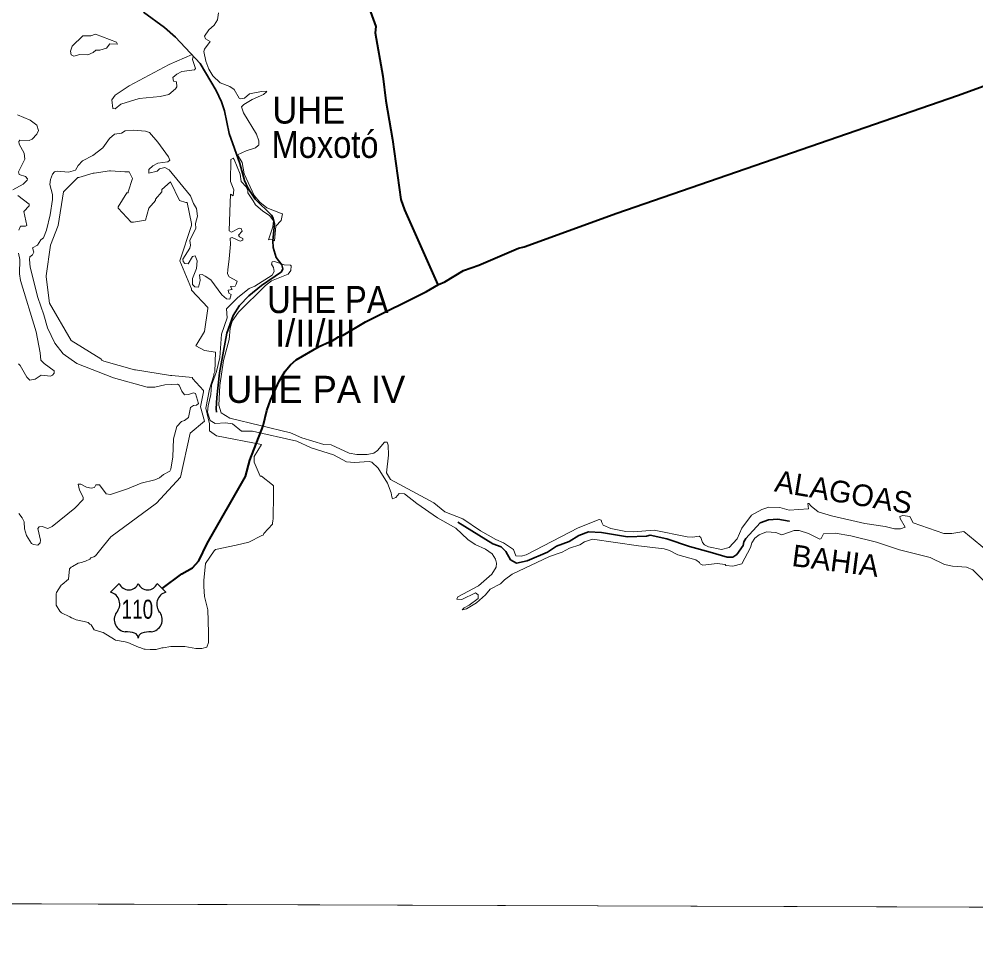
# Model space of a CAD drawing. Extents: x 553962 to 842807, y 8883888 to 9032388.
# Drawn here: x 580395 to 583927, y 8909822 to 8913255 of the extents above; entities that cross this region are included whole.
import ezdxf
from ezdxf.enums import TextEntityAlignment as Align

# ---------------------------------------------------------------- set-up
doc = ezdxf.new("R2010")
doc.units = 0
doc.header["$LTSCALE"] = 200
doc.linetypes.add('LONG_DASH_SHORT_DASH', pattern=[9.9, 6, -1.2, 1.5, -1.2])
doc.layers.add('6', color=7, linetype='Continuous', lineweight=13)

msp = doc.modelspace()

# ---------------------------------------------------------------- linework, layer by layer
at = {"layer": '6', "lineweight": 25}
for p, q in [((580732.9, 8911139.1), (580764.9, 8911171.1)), ((580904.8, 8911171.1), (580936.8, 8911139.1))]:
    msp.add_line(p, q, dxfattribs=at)
at = {"layer": '6'}
msp.add_line((574653.9, 8910009.3), (626625.7, 8909822.1), dxfattribs=at)
for points in [[(585645.8, 8921027.3), (574684.9, 8921064.7), (574653.9, 8910009.3), (585614.8, 8909969.8)], [(580677.4, 8913199.3), (580754.6, 8913169.1), (580757.7, 8913161.8), (580729.4, 8913163.2), (580717.7, 8913147), (580692.7, 8913140.2), (580677.9, 8913140.2), (580669, 8913131.7), (580648.6, 8913122.4), (580619.7, 8913123.6), (580597.1, 8913117.7), (580587.8, 8913122.8), (580585.2, 8913136.5), (580590.4, 8913155), (580629.9, 8913192.5), (580660.4, 8913193.7)], [(580749.7, 8912974.1), (580801.2, 8913008.5), (580948.9, 8913087.1), (581033.9, 8913124), (581037.3, 8913116.8), (581035.2, 8913105.4), (581045.7, 8913072.2), (581042.7, 8913067.9), (580996, 8913061.1), (580977.8, 8913051.8), (580962.2, 8913039.1), (580964.6, 8913025.5), (580976, 8913023.8), (580976.9, 8913004.7), (580972.7, 8912997.5), (580948.1, 8912976.6), (580915.4, 8912968.6), (580838.8, 8912961.7), (580770.9, 8912941.3), (580750.1, 8912923.1), (580741.6, 8912925.3), (580737.8, 8912956.3)]]:
    msp.add_lwpolyline(points, close=True, dxfattribs=at)
at = {"layer": '6', "linetype": 'LONG_DASH_SHORT_DASH', "lineweight": 35}
for points in [[(580854, 8913279.9), (580932.2, 8913223.8), (580972.1, 8913187.7), (581063.2, 8913090.6), (581122.5, 8912991.5), (581142, 8912949.8), (581153.2, 8912915.6), (581171, 8912832.2), (581209.9, 8912721.7), (581227.6, 8912659.4), (581239.2, 8912631.8), (581266.5, 8912590.3), (581326.2, 8912531.5), (581332.6, 8912519.4), (581337.8, 8912498.5), (581331.8, 8912436.4), (581333.1, 8912411.1), (581343.9, 8912375), (581365.1, 8912348.2), (581368.5, 8912332.5), (581364.2, 8912321.3), (581289.9, 8912271.7), (581243.5, 8912233.1), (581208.6, 8912197.7), (581185.2, 8912160.5), (581161.6, 8912095.9), (581134.3, 8911949.1), (581124.7, 8911857.9), (581122.5, 8911815.6), (581124, 8911803.1)], [(582014.6, 8911397.4), (582144.1, 8911317), (582174.9, 8911306.2), (582192.1, 8911288.9), (582208.6, 8911258.7), (582231.6, 8911246.5), (582271.2, 8911254.3), (582345.6, 8911286.3), (582378.5, 8911308.3), (582425.2, 8911326.1), (582461.6, 8911347.7), (582496.6, 8911362.4), (582544.5, 8911359.4), (582641.4, 8911343.8), (582710.6, 8911346), (582724.4, 8911349.4), (582786.7, 8911336.4), (582869.7, 8911307.5), (582946.6, 8911287.2), (583008.9, 8911268.1), (583029.6, 8911268.6), (583045.2, 8911277.6), (583067.7, 8911311.3), (583070.7, 8911325.2), (583077.6, 8911337.3), (583130.3, 8911394.8), (583161.9, 8911405.6), (583196.6, 8911409.1), (583238, 8911401.7), (583238.9, 8911401.7)]]:
    msp.add_lwpolyline(points, dxfattribs=at)
at = {"layer": '6'}
for points in [[(581309.8, 8912988.2), (581309.8, 8912988.2), (581289.7, 8912987.7), (581245.5, 8912978.7), (581227.2, 8912963.4), (581212, 8912960.1), (581207.2, 8912962.6), (581188.9, 8912994.9), (581172.8, 8913005.9), (581137.1, 8913019.9), (581110.7, 8913045.9), (581096, 8913070), (581084, 8913099.8), (581076.8, 8913135.4), (581079.3, 8913144), (581100.6, 8913172.4), (581083.2, 8913182.3), (581079.8, 8913192.1), (581095.1, 8913214.9), (581115, 8913232.4), (581127.7, 8913252.7), (581131.6, 8913278.4)], [(581277.8, 8912788.2), (581279.5, 8912789.6), (581280, 8912805.1), (581271, 8912830.4), (581223.8, 8912908.6), (581216.6, 8912930.4), (581224.7, 8912939.7), (581254.8, 8912957.9), (581296.7, 8912976.6), (581308.1, 8912986.6), (581309.8, 8912988.2)], [(580388.5, 8912901.4), (580436.2, 8912882.3), (580460.3, 8912862.7), (580466.7, 8912844), (580460.3, 8912829.6), (580443.8, 8912811), (580432.7, 8912806.3), (580397.9, 8912807.9), (580394.1, 8912802.5), (580395.3, 8912793), (580413.2, 8912759.9), (580416.6, 8912737.9), (580392.8, 8912690.9), (580395.3, 8912681.4), (580418.7, 8912673.7), (580425.9, 8912664.7), (580424.9, 8912660.4), (580409.4, 8912645.7), (580371.5, 8912623.9)], [(580896.6, 8911553.8), (580912.7, 8911561), (580928, 8911573.3), (580951, 8911585.2), (580955.3, 8911593.3), (580962.1, 8911639.2), (580965.5, 8911704.7), (580977.3, 8911751.3), (580993.9, 8911768.7), (581005.5, 8911772.6), (581020.3, 8911784.5), (581028.3, 8911821), (581038.6, 8911828.7), (581049.6, 8911829.9), (581056.8, 8911835.1), (581046.7, 8911872.7), (581039.4, 8911875.4), (581020.8, 8911869.1), (581005.8, 8911868.2), (580995.2, 8911881.4), (580986.3, 8911903.8), (580980.3, 8911907.2), (580933.2, 8911905.1), (580895.8, 8911896.2), (580867.6, 8911895.4), (580743.7, 8911929.8), (580608.6, 8911983.8), (580557.2, 8912019.4), (580527, 8912059), (580499.4, 8912115), (580486.1, 8912163.4), (580463.7, 8912227.1), (580435.7, 8912339.3), (580433.1, 8912367.4), (580435.2, 8912376.6), (580444.6, 8912384.8), (580449.3, 8912394.6), (580444.7, 8912409.9), (580462.4, 8912419.7), (580475.2, 8912439.6), (580484.5, 8912446.8), (580496.3, 8912475.7), (580510, 8912532.2), (580518.5, 8912588.3), (580518.5, 8912607), (580508.3, 8912644.4), (580510.9, 8912663), (580518.7, 8912681.9), (580525.8, 8912690.7), (580535.5, 8912693.2), (580577, 8912689.8), (580577, 8912689.8), (580602.6, 8912697.5), (580612.9, 8912714.1), (580629, 8912731.5), (580667.3, 8912751.5), (580704.2, 8912779), (580728.9, 8912814.4), (580747.1, 8912830.5), (580772.6, 8912833.5), (580786.6, 8912842.8), (580816.8, 8912845.3), (580861.8, 8912841.5), (580876.7, 8912835.6), (580907.3, 8912800.7), (580946.8, 8912745.9), (580951.8, 8912734.5), (580944.1, 8912728.4), (580907.7, 8912722.4), (580888.1, 8912713.2), (580873.7, 8912699.1), (580873.7, 8912686.1), (580905.1, 8912693.7), (580912.8, 8912702.2), (580933.6, 8912706.4), (580948.5, 8912698.3), (581027.9, 8912601.9), (581039, 8912573.9), (581050.5, 8912555), (581053.4, 8912527.1), (581046.2, 8912500.8), (581047.9, 8912483.1), (581025, 8912437.1), (581027.9, 8912419.8), (581024.9, 8912409), (580999.5, 8912368.6), (581000.8, 8912359.3), (581007.1, 8912353), (581019.3, 8912350.8), (581035.6, 8912378), (581045.2, 8912381), (581052.5, 8912362.4), (581049.6, 8912334.3), (581034.7, 8912296.8), (581034.8, 8912275.2), (581043.2, 8912266.3), (581057.1, 8912265), (581063.6, 8912289.2), (581060.7, 8912310.8), (581070.9, 8912312.5), (581081.6, 8912305.8)], [(581366.5, 8912535.8), (581309.1, 8912558.6), (581283.7, 8912578.6), (581262.3, 8912603.9), (581262.3, 8912603.9), (581225.9, 8912683.5), (581218.3, 8912725.1), (581201.7, 8912753.5), (581233.6, 8912768.4), (581267.9, 8912779.9), (581277.8, 8912788.2)], [(581172.7, 8912543.7), (581175, 8912608.9), (581185.1, 8912601.8), (581187.7, 8912624), (581174.9, 8912654.7), (581176.2, 8912736.1), (581185.3, 8912741.2), (581189.3, 8912737.1), (581210.6, 8912682.6), (581215.3, 8912655.5), (581233.2, 8912635.8), (581239.9, 8912622.3), (581240, 8912613.3), (581258.5, 8912584.3)], [(580733.2, 8911343.8), (580902, 8911467.3), (580990.8, 8911564.2), (581027.1, 8911725.6), (581079.6, 8911770), (581064.5, 8911823.6), (581075.6, 8911879), (581075.6, 8911883.1), (581035.2, 8911927.5), (581035.2, 8911931.5), (580958.5, 8911939.6), (580954.5, 8911939.6), (580825.3, 8911959.8), (580821.3, 8911959.8), (580708.3, 8911992), (580700.2, 8911996.1), (580696.2, 8912000.1), (580587.3, 8912068.7), (580506.6, 8912206), (580494.4, 8912302.9), (580494.4, 8912306.9), (580510.6, 8912419.9), (580538.8, 8912492.6), (580559, 8912617.7), (580611.5, 8912670.2), (580615.5, 8912670.2), (580668, 8912686.4), (580672, 8912686.4), (580728.5, 8912694.4), (580732.5, 8912694.4), (580785, 8912690.4), (580793.1, 8912690.4), (580797.1, 8912690.4), (580801.1, 8912690.4), (580813.2, 8912666.2), (580797.1, 8912617.7), (580797.1, 8912613.7), (580793.1, 8912613.7), (580760.8, 8912561.2), (580760.8, 8912557.2), (580809.2, 8912504.7), (580813.2, 8912504.7), (580817.3, 8912504.7), (580861.7, 8912512.8), (580873.8, 8912557.2), (580898, 8912585.4), (580898, 8912589.5), (580922.2, 8912617.7), (580922.2, 8912621.8), (580922.2, 8912625.8), (580954.5, 8912654.1), (580986.8, 8912585.4), (581011, 8912577.4), (581015, 8912577.4), (581031.2, 8912500.7), (581031.2, 8912496.6), (581031.2, 8912492.6), (580988.2, 8912362.7), (581031.2, 8912258.5), (581031.2, 8912254.4), (581091.7, 8912189.8), (581091.7, 8912185.8), (581079.6, 8912101), (581047.3, 8912048.6)], [(580389.8, 8912603.1), (580432.7, 8912571.7), (580432.5, 8912565.6), (580412.3, 8912544.5), (580423.3, 8912493.2), (580418.2, 8912489.8), (580400.4, 8912490.6), (580394.5, 8912476.2)], [(581258.5, 8912584.3), (581268.3, 8912568.8), (581295.3, 8912545.3), (581319, 8912529.6), (581333.8, 8912510.2), (581332.8, 8912500.7)], [(581218.2, 8912471.5), (581214.4, 8912482.3), (581208, 8912482.9), (581179.6, 8912467.7), (581170.2, 8912473.2), (581172.7, 8912543.7)], [(581337.2, 8912437), (581338.1, 8912436.6), (581342.3, 8912490.1), (581362.3, 8912511), (581366.8, 8912535.7), (581366.5, 8912535.8)], [(581169.9, 8912369.9), (581175.8, 8912423.6), (581174.5, 8912446.3), (581181.3, 8912448.5), (581211, 8912434.9), (581220.8, 8912438.5), (581220.4, 8912445.1), (581208.9, 8912451.1), (581205.5, 8912456.7), (581218.2, 8912471.5), (581218.2, 8912471.5)], [(581332.8, 8912500.7), (581331.5, 8912488.3), (581315.9, 8912439.5), (581316.2, 8912439.6), (581316.2, 8912440.5)], [(581316.2, 8912439.6), (581324.1, 8912442.3), (581337.2, 8912437)], [(580393.2, 8912391), (580397.9, 8912367.4), (580397, 8912313.8), (580400, 8912290.1), (580457.8, 8912099.8), (580473.1, 8912022.4), (580474.8, 8911995.7), (580487.1, 8911983.3), (580524.9, 8911956.1), (580524.5, 8911947.6), (580518.1, 8911940), (580510.8, 8911937), (580476, 8911940), (580454.4, 8911926), (580434.4, 8911921.7), (580423.8, 8911932.8), (580398.7, 8911976.5), (580392.2, 8911981.7)], [(581196.1, 8912276.3), (581200.4, 8912287), (581169.9, 8912302.8), (581163.9, 8912314.7), (581165.4, 8912328.8), (581169.9, 8912369.9)], [(581135.5, 8911901.6), (581149.3, 8911994.6), (581170.2, 8912071.5), (581173.7, 8912113.4), (581181.2, 8912140.2), (581205.4, 8912173.1), (581304.6, 8912271.9), (581326.6, 8912288.6), (581388, 8912312.8), (581398.3, 8912327.2), (581399.7, 8912343.6), (581396.9, 8912346.6), (581374.1, 8912347), (581338.1, 8912359.7), (581329.6, 8912358.2), (581327, 8912349.8), (581333.7, 8912337.4), (581336.7, 8912322.7), (581329, 8912309.2), (581265.5, 8912268.8), (581244.2, 8912259.8), (581202.1, 8912226.9), (581160.5, 8912185.1), (581163.3, 8912151.7), (581142.6, 8912091.4), (581136.6, 8912006), (581124.1, 8911954.1), (581104.7, 8911903.6), (581102.9, 8911869.2), (581093, 8911827.2), (581091, 8911804.1), (581100.6, 8911772.3), (581118.2, 8911761.8), (581156.8, 8911764.7), (581182.7, 8911761.1), (581215.5, 8911733.5), (581257.2, 8911733.9), (581420.6, 8911696.1), (581473.7, 8911672.5), (581556.1, 8911645.9), (581603.5, 8911620.1), (581633.2, 8911618), (581687.3, 8911621.4), (581697.3, 8911618.8), (581720.2, 8911596.8), (581754.8, 8911541.3), (581768.5, 8911506.1), (581770.8, 8911491.1), (581773.4, 8911483.1), (581785.4, 8911488.5), (581798.7, 8911502.9), (581818.2, 8911502.4), (581863, 8911466.3), (581940, 8911413.8), (582006.9, 8911375.9), (582051.8, 8911333.2), (582079.1, 8911315.5), (582116.8, 8911298.3), (582141.3, 8911280.1), (582153.2, 8911260.5), (582157.4, 8911246.5), (582156.8, 8911231.9), (582140.6, 8911205), (582091.4, 8911162.7), (582014.5, 8911121.4)], [(581081.6, 8912305.8), (581103, 8912292.4), (581143.5, 8912237.3), (581160.1, 8912222.1), (581173.1, 8912220.7), (581178.4, 8912238.5), (581169, 8912243.4), (581167.3, 8912254.3), (581181.7, 8912256.8), (581176, 8912267.4), (581193.2, 8912269.3), (581196.1, 8912276.3)], [(581047.3, 8912048.6), (581079.2, 8912031.7), (581120.6, 8912025.3), (581117.4, 8911952), (581114.3, 8911945.6), (581114.3, 8911939.2), (581098.3, 8911888.2), (581083.9, 8911818.2), (581098.3, 8911761), (581098.3, 8911735.2), (581123.8, 8911716), (581289.6, 8911684.2)], [(582634.4, 8911363.2), (582579.1, 8911373.6), (582550.8, 8911386.8), (582545.9, 8911396.6), (582544.2, 8911404.8), (582536.6, 8911407.9), (582459.2, 8911376.8), (582266.9, 8911277), (582247.9, 8911272), (582228.9, 8911273), (582219.8, 8911296.8), (582183.2, 8911321.6), (582155, 8911333.2), (582098.2, 8911365.9), (582032.6, 8911409.3), (581966.1, 8911435.9), (581926.1, 8911468.6), (581766.4, 8911554.5), (581751, 8911579.8), (581759.2, 8911645), (581757, 8911682.3), (581753.9, 8911693), (581744.2, 8911692.6), (581718.2, 8911662.4), (581704.6, 8911652.6), (581679.8, 8911647.1), (581642.2, 8911646.8), (581613.1, 8911652.5), (581547.6, 8911683.5), (581519.6, 8911684), (581438.5, 8911709), (581397.4, 8911727.8), (581173.1, 8911780.9), (581140.4, 8911800.9), (581132.1, 8911829.1), (581135.5, 8911901.6)], [(581091.6, 8911074.3), (581090.1, 8911078.7), (581079.7, 8911123.2), (581076.8, 8911160.2), (581076.8, 8911182.4), (581082.7, 8911244.6), (581115.3, 8911292), (581119.7, 8911296.5), (581196.7, 8911312.8), (581242.6, 8911323.1), (581291.5, 8911348.3), (581295.9, 8911349.8), (581298.9, 8911355.7), (581330, 8911389.8), (581330, 8911395.7), (581331.5, 8911400.1), (581332.9, 8911412), (581332.9, 8911423.8), (581334.4, 8911487.5), (581334.4, 8911492), (581334.4, 8911496.4), (581334.4, 8911532), (581330, 8911534.9), (581290, 8911567.5), (581285.5, 8911567.5), (581263.3, 8911619.3), (581263.3, 8911640.1), (581289.6, 8911684.2)], [(581289.6, 8911684.2), (581263.3, 8911640.1), (581263.3, 8911619.3), (581285.5, 8911567.5), (581290, 8911567.5), (581330, 8911534.9), (581334.4, 8911532), (581334.4, 8911496.4), (581334.4, 8911492), (581334.4, 8911487.5), (581332.9, 8911423.8), (581332.9, 8911412), (581331.5, 8911400.1), (581330, 8911395.7), (581330, 8911389.8), (581298.9, 8911355.7), (581295.9, 8911349.8), (581291.5, 8911348.3), (581242.6, 8911323.1), (581196.7, 8911312.8), (581119.7, 8911296.5), (581115.3, 8911292), (581082.7, 8911244.6), (581076.8, 8911182.4), (581076.8, 8911160.2), (581079.7, 8911123.2), (581090.1, 8911078.7), (581091.6, 8911074.3)], [(580394, 8911428.9), (580406.8, 8911413.6), (580413.2, 8911398.7), (580415.3, 8911373.2), (580422.9, 8911347.7), (580441.2, 8911319.3), (580447.6, 8911315), (580464.1, 8911312.5), (580473, 8911320.9), (580474.3, 8911331.5), (580464.2, 8911373.9), (580469.6, 8911380), (580480.7, 8911382.1), (580501.4, 8911373.7), (580516.9, 8911381.3), (580601.1, 8911449.4), (580631.4, 8911481.8), (580631.6, 8911490.3), (580617.5, 8911516), (580612.5, 8911537.2), (580623.1, 8911537.2), (580644.2, 8911526.6), (580661.3, 8911523.2), (580673.6, 8911525.3), (580678.7, 8911535.1), (580691.8, 8911535.1), (580716.5, 8911501.6), (580732.2, 8911499.4), (580794.7, 8911520.2), (580845.5, 8911541.4), (580896.6, 8911553.8)], [(583966.5, 8911293.9), (583882.2, 8911363.2), (583838.3, 8911355.7), (583808.5, 8911355.2), (583696.2, 8911394.6), (583683, 8911417.9), (583657.1, 8911421.6), (583646.5, 8911418.1), (583648, 8911410.9), (583666.4, 8911379.1), (583648.5, 8911372.9), (583626.9, 8911373), (583592.4, 8911382), (583517.2, 8911392.7), (583393.6, 8911421.1), (583345.3, 8911435.9), (583319.1, 8911456.7), (583310.5, 8911466.5), (583307.1, 8911466.5), (583309.5, 8911446.9), (583237.7, 8911441.4), (583203.3, 8911451.7), (583163.4, 8911452.9), (583136.7, 8911443.9), (583099.1, 8911422.9), (583062.9, 8911375.8), (583045.7, 8911335.9), (583016.8, 8911303.6), (582988.5, 8911297.2), (582940.1, 8911306.8), (582925.6, 8911313.4), (582918.1, 8911322.8), (582911.8, 8911341.3), (582906, 8911346.2), (582880.8, 8911342.6), (582861.2, 8911343.5), (582740.1, 8911367.8), (582663.3, 8911361.8), (582634.4, 8911363.2)], [(580733.2, 8911343.8), (580706.6, 8911309.8), (580677, 8911272.8), (580671.1, 8911269.8), (580659.2, 8911265.3), (580656.3, 8911260.9), (580640, 8911253.5), (580635.5, 8911252), (580625.2, 8911249.1), (580613.3, 8911246.1), (580592.6, 8911234.2), (580586.7, 8911231.3), (580580.7, 8911225.4), (580577.8, 8911186.8), (580554.1, 8911167.6), (580549.7, 8911164.6), (580533.4, 8911138), (580531.9, 8911133.5), (580531.9, 8911123.2), (580531.9, 8911095), (580531.9, 8911090.6), (580545.2, 8911068.4), (580551.1, 8911062.4), (580582.2, 8911047.6), (580588.2, 8911044.7), (580592.6, 8911043.2), (580605.9, 8911037.2), (580611.8, 8911035.8), (580616.3, 8911034.3), (580635.5, 8911031.3), (580640, 8911029.8), (580650.3, 8911026.9), (580656.3, 8911021), (580660.7, 8911018), (580665.1, 8911012.1), (580668.1, 8911006.2), (580672.6, 8911000.2), (580700.7, 8910991.3), (580705.1, 8910989.9), (580746.6, 8910964.7), (580751, 8910961.7), (580786.6, 8910955.8), (580796.9, 8910952.8), (580835.4, 8910936.5), (580841.3, 8910935.1), (580856.2, 8910929.1), (580860.6, 8910929.1), (580878.4, 8910927.7), (580884.3, 8910927.7), (580894.7, 8910927.7), (580900.6, 8910927.7), (580921.3, 8910933.6), (580927.2, 8910933.6), (580955.3, 8910938), (580967.2, 8910938), (581007.2, 8910938), (581047.2, 8910930.6), (581069.4, 8910930.6), (581088.6, 8910936.5), (581094.5, 8910952.8), (581094.5, 8910957.3), (581094.5, 8910994.3), (581093.1, 8911026.9), (581093.1, 8911032.8), (581091.6, 8911074.3)], [(581091.6, 8911074.3), (581093.1, 8911032.8), (581093.1, 8911026.9), (581094.5, 8910994.3), (581094.5, 8910957.3), (581094.5, 8910952.8), (581088.6, 8910936.5), (581069.4, 8910930.6), (581047.2, 8910930.6), (581007.2, 8910938), (580967.2, 8910938), (580955.3, 8910938), (580927.2, 8910933.6), (580921.3, 8910933.6), (580900.6, 8910927.7), (580894.7, 8910927.7), (580884.3, 8910927.7), (580878.4, 8910927.7), (580860.6, 8910929.1), (580856.2, 8910929.1), (580841.3, 8910935.1), (580835.4, 8910936.5), (580796.9, 8910952.8), (580786.6, 8910955.8), (580751, 8910961.7), (580746.6, 8910964.7), (580705.1, 8910989.9), (580700.7, 8910991.3), (580672.6, 8911000.2), (580668.1, 8911006.2), (580665.1, 8911012.1), (580660.7, 8911018), (580656.3, 8911021), (580650.3, 8911026.9), (580640, 8911029.8), (580635.5, 8911031.3), (580616.3, 8911034.3), (580611.8, 8911035.8), (580605.9, 8911037.2), (580592.6, 8911043.2), (580588.2, 8911044.7), (580582.2, 8911047.6), (580551.1, 8911062.4), (580545.2, 8911068.4), (580531.9, 8911090.6), (580531.9, 8911095), (580531.9, 8911123.2), (580531.9, 8911133.5), (580533.4, 8911138), (580549.7, 8911164.6), (580554.1, 8911167.6), (580577.8, 8911186.8), (580580.7, 8911225.4), (580586.7, 8911231.3), (580592.6, 8911234.2), (580613.3, 8911246.1), (580625.2, 8911249.1), (580635.5, 8911252), (580640, 8911253.5), (580656.3, 8911260.9), (580659.2, 8911265.3), (580671.1, 8911269.8), (580677, 8911272.8), (580706.6, 8911309.8), (580733.2, 8911343.8)], [(583062.7, 8911243.2), (583095.4, 8911304), (583099.7, 8911321.3), (583111.2, 8911338.2), (583126.6, 8911350.5), (583153.6, 8911361.8), (583188.6, 8911359.7), (583211.3, 8911350.5), (583256.3, 8911366.4), (583274.7, 8911366.4), (583309.8, 8911355.4), (583350.5, 8911335.3), (583355.5, 8911337.7), (583364.5, 8911354.3), (583407.8, 8911356.6), (583465.7, 8911346.7), (583560.9, 8911323.1), (583645.6, 8911294.8), (583758.9, 8911266.5), (583811.2, 8911241.3), (583841, 8911234.7), (583892.8, 8911231.2), (583915.5, 8911221.6), (583973.2, 8911163.9)], [(582014.5, 8911121.4), (582010.5, 8911113), (582029.1, 8911112.6), (582080.3, 8911136.5), (582089.3, 8911129), (582089.3, 8911116.2), (582056.3, 8911091.3), (582038, 8911081.5), (582030.9, 8911073.5), (582047.2, 8911077.7), (582084.2, 8911100), (582117.1, 8911129.1), (582134.6, 8911150.4), (582172.3, 8911170.2), (582186.7, 8911184.5), (582215.5, 8911205.5), (582353.6, 8911270.2), (582399.6, 8911286.5), (582427.2, 8911301.9), (582464.8, 8911313.9), (582482.7, 8911325), (582512.2, 8911335.3), (582681.7, 8911309.6), (582777, 8911299.2), (582796.6, 8911293), (582827.3, 8911276.8), (582893.4, 8911258.7), (582906.7, 8911249.2), (582909.6, 8911243.5), (582918.9, 8911239.1), (582972.2, 8911244.5), (583002.2, 8911240.8), (583003.6, 8911237.4), (583029.7, 8911234.8), (583062.7, 8911243.2)]]:
    msp.add_lwpolyline(points, dxfattribs=at)
at = {"layer": '6', "lineweight": 40}
for points in [[(581692.8, 8913282), (581711.4, 8913227.6), (581709.7, 8913204.2), (581738.2, 8913043.9), (581749.4, 8912952.6), (581773.3, 8912810.4), (581804.3, 8912589.4), (581818.2, 8912550.3), (581941.2, 8912274)], [(581088.7, 8911319.2), (581230.6, 8911565.6), (581246.6, 8911626.2), (581295.9, 8911753.5), (581309.3, 8911809.4), (581322.7, 8911848.3), (581355.5, 8911918.2), (581377.7, 8911955.6), (581396.6, 8911978.5), (581417.4, 8911997.1), (581502.6, 8912046.4), (581540.6, 8912063.6), (581547.6, 8912064.2), (581573.9, 8912081.4), (581591.7, 8912087.9), (581673.8, 8912137.2), (581899.5, 8912248.7), (581943.6, 8912275.5), (581967, 8912284.7), (582035.6, 8912326.1), (582092.7, 8912345.9), (582239.2, 8912409.1), (582260, 8912414.3), (582602, 8912537.9), (583859, 8912972.9), (584080.2, 8913052.4)], [(580922.7, 8911153.1), (580996.2, 8911207.1), (581034.8, 8911228.8), (581058, 8911254.4), (581088.7, 8911319.2)]]:
    msp.add_lwpolyline(points, dxfattribs=at)
at = {"layer": '6', "lineweight": 25}
for centre, radius, start, end in [((580799.9, 8911184.5), 37.4, 200.9593, 339.0407), ((580869.8, 8911184.5), 37.4, 200.9593, 339.0407), ((580720.5, 8911094.7), 46.1, 317.5721, 74.3689), ((580949.2, 8911094.7), 46.1, 105.6277, 222.4279), ((580791.2, 8911037.7), 44.9, 144.7373, 264.6578), ((580878.5, 8911037.7), 44.9, 275.3422, 35.2627), ((580786.8, 8910875), 118, 72.8937, 89.9006), ((580816, 8910969.7), 18.9, 357.6934, 72.9296), ((580853.7, 8910969.7), 18.9, 107.0704, 182.3065), ((580882.9, 8910875), 118, 90.0994, 107.1063)]:
    msp.add_arc(centre, radius, start, end, dxfattribs=at)

# ---------------------------------------------------------------- texts
at = {"layer": '6'}
for s, height, width, p in [('UHE', 100, 0.95, (581464.1, 8912869.1)), ('Moxotó', 100, 0.9, (581524.5, 8912742.3)), ('UHE PA', 100, 0.9, (581534.8, 8912169.4)), ('110', 70, 0.75, (580831.6, 8911041.1))]:
    msp.add_text(s, height=height, dxfattribs=dict(at, width=width)).set_placement(p, align=Align.CENTER)
for s, p in [('I/II/III', (581488.8, 8912045.7)), ('UHE PA IV', (581490, 8911837.9))]:
    msp.add_text(s, height=100, dxfattribs=at).set_placement(p, align=Align.CENTER)
for s, rotation, p in [('ALAGOAS', 350.452, (583432.5, 8911469.1)), ('BAHIA', 352.646, (583404, 8911215.6))]:
    msp.add_text(s, height=80, rotation=rotation, dxfattribs=at).set_placement(p, align=Align.CENTER)

doc.saveas('drawing.dxf')
